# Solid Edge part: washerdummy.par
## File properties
Author: morva
Template: iso metric part.par
Last saved by: morva
Revision: 2
Application: Solid Edge
Density: 1190.000 kg/m^3
Accuracy: 0.990
Username: morva
Material: Polycarbonate
Face Style: Red
Fill Style: ANSI34(Plastic)
Virtual Style: ANSI34(Plastic)
Grouping: Non-metals\Plastics
LibraryName: Materials
Coef. of Thermal Exp: 6.8e-05
Thermal Conductivity: 2.3
Specific Heat: 1265.0
Modulus of Elasticity: 2240796025.0
Poisson's Ratio: 0.35
Yield Stress: 58605434.5
Ultimate Stress: 0.0
Elongation: 0.0
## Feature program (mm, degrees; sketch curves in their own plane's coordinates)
sketch for "unnamed Protrusion 1" #1 plane through (0, 0, 0) normal (0, 0, 1) x-axis (1, 0, 0)
  circle centre (0, 0) radius 10
sketch for "unnamed Protrusion 1" #2 plane through (0, 0, 0) normal (0, 0, 1) x-axis (1, 0, 0)
  circle centre (0, 0) radius 15
extrude "unnamed Protrusion 1" add finite 2.3 symmetric
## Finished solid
Body 1: solid body, 4 faces, 4 edges, 0 vertices.
  Faces by surface: cylinder 2, plane 2
  Edges by curve: circle 4
Bounding box of the edges (mm): 30.000 x 30.000 x 2.300, from (-15, -15, -1.15) to (15, 15, 1.15).
Cylindrical faces by radius (mm): R10 x1, R15 x1
Planar faces by outward normal: +z 1, -z 1
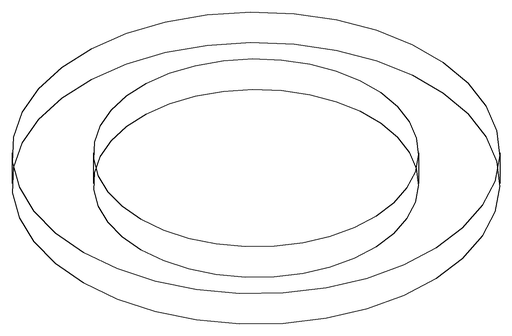
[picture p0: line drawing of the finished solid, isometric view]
